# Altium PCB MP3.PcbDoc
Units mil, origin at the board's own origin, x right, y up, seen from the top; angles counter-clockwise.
Board outline 5023.23 x 3354.25 mil, 2 copper layers (Top Layer, Bottom Layer); 77 components, 66 nets, 306 pads, 116 vias.
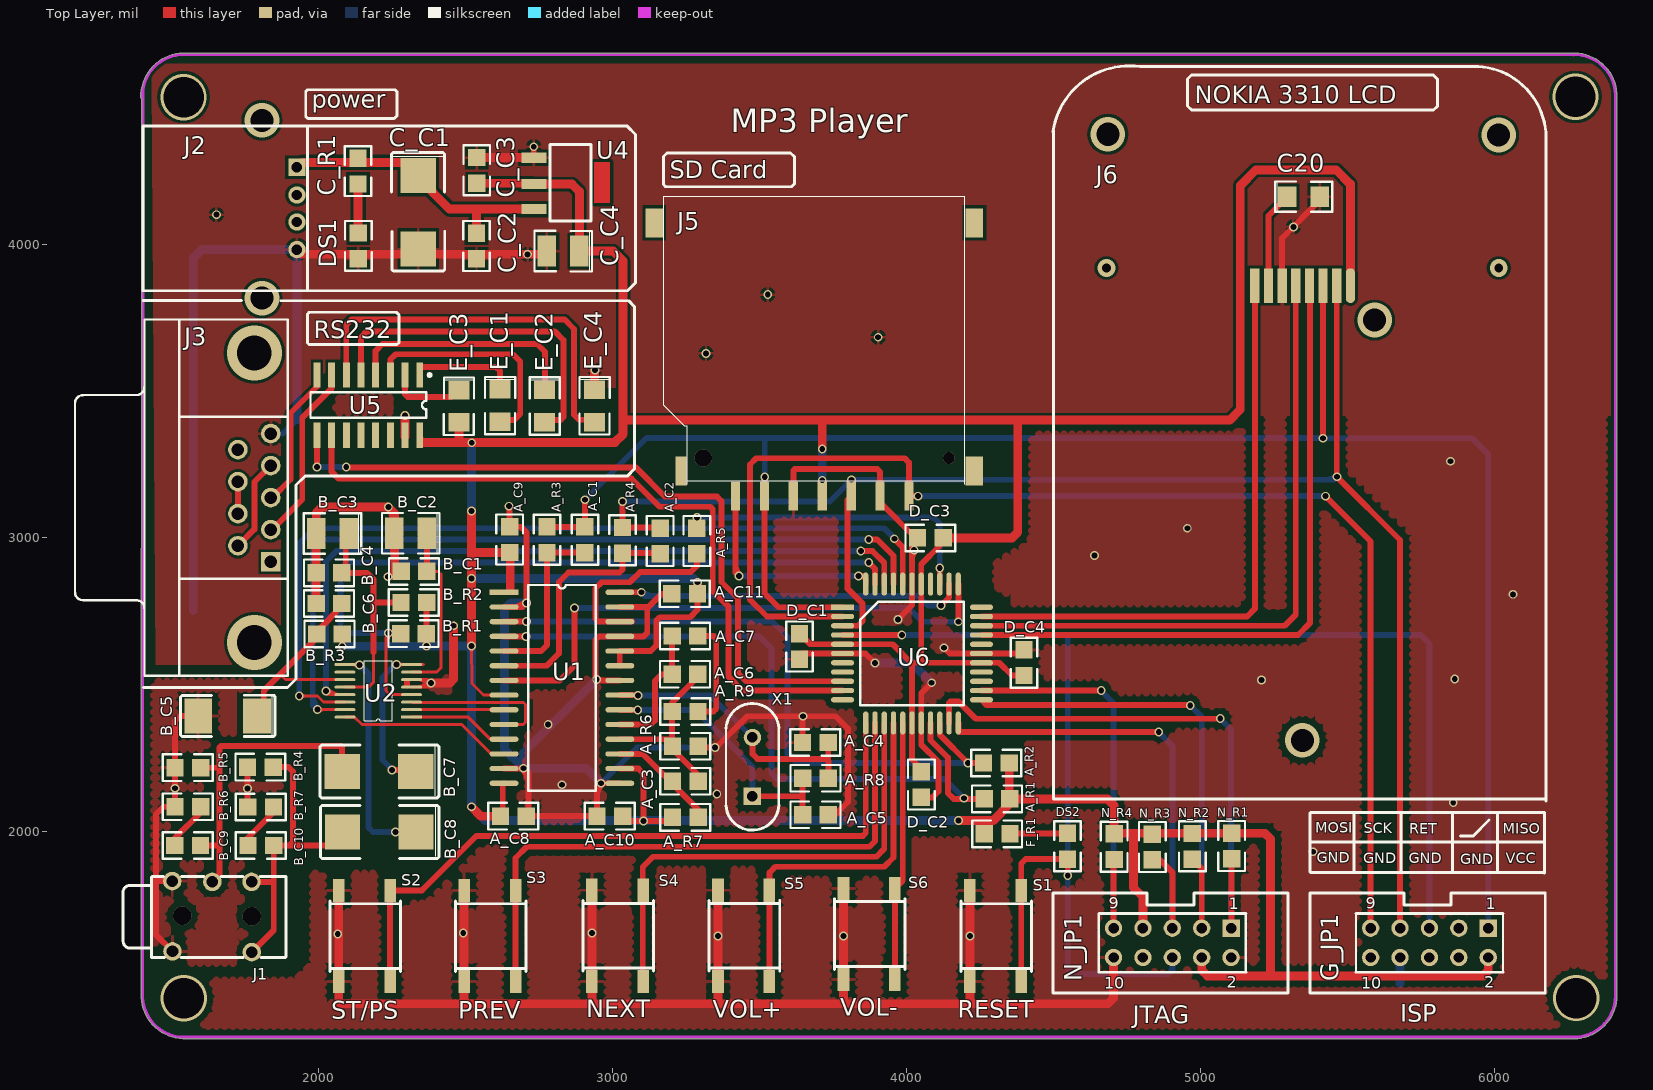
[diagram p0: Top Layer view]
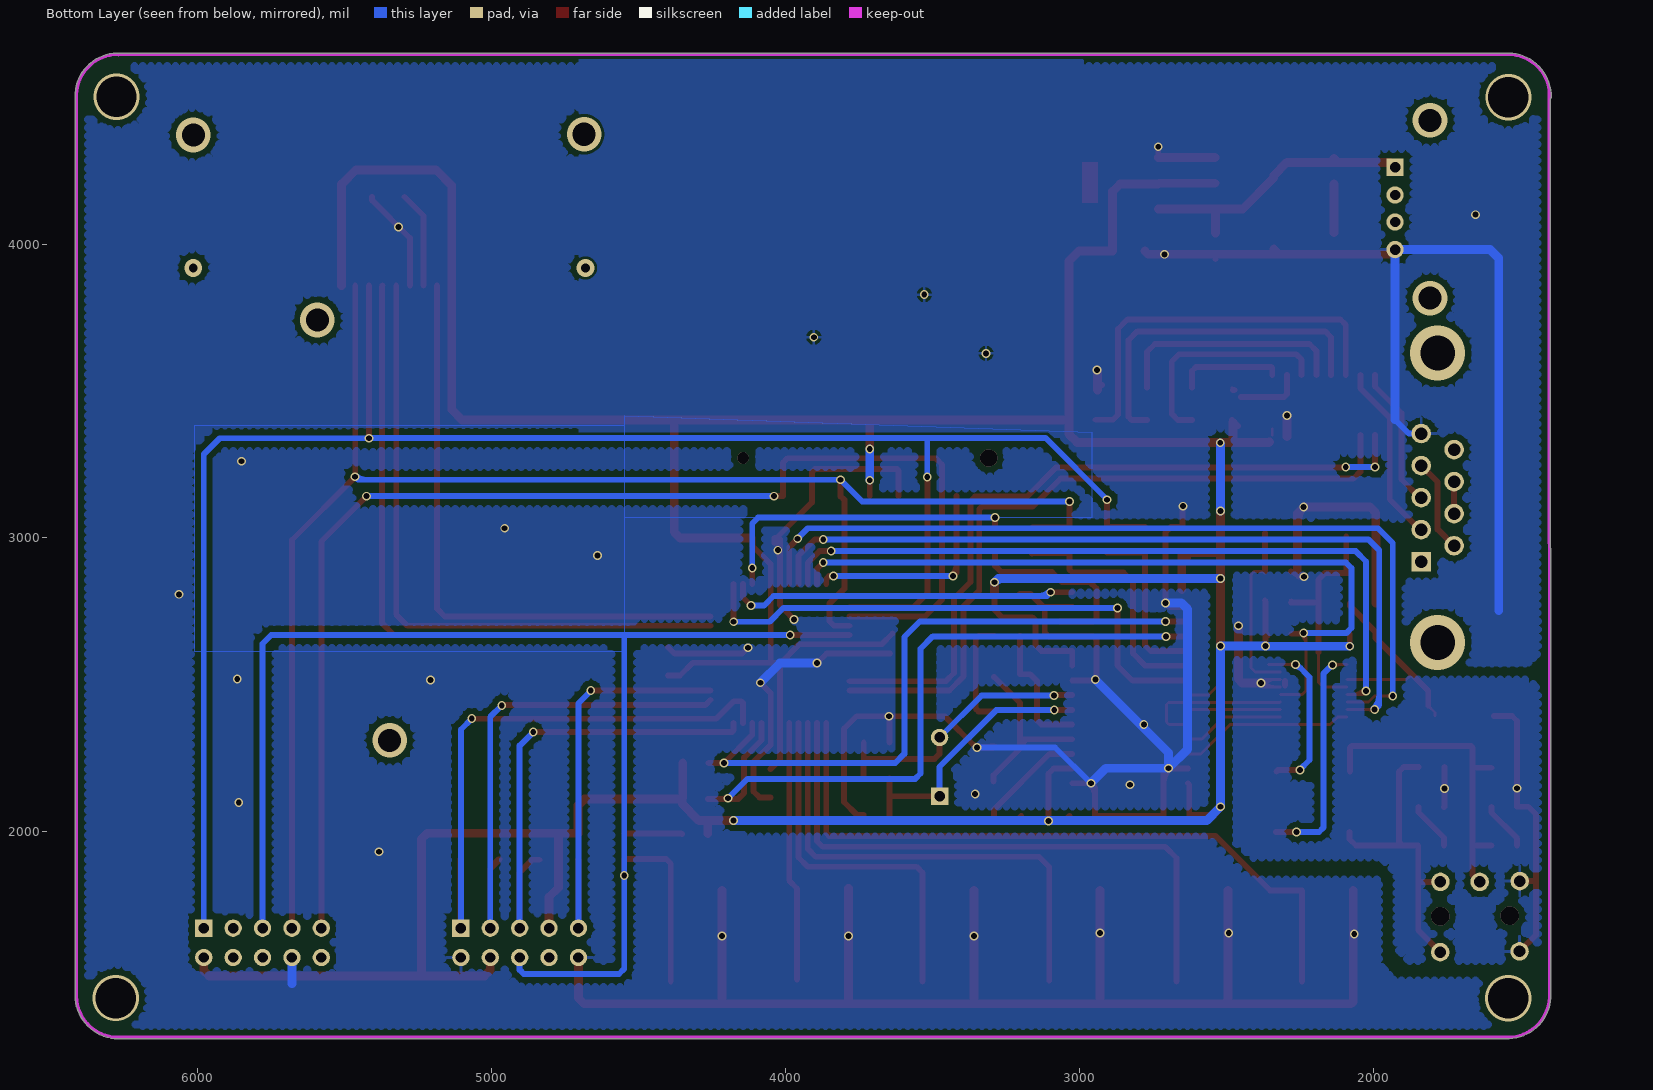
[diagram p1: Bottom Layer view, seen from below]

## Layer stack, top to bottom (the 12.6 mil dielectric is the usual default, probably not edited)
Top Layer: signal copper 1.4
Dielectric: dielectric 12.6, FR-4, Dk 4.8
Bottom Layer: signal copper 1.4

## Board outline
1395.99,1435.72 cw(c1543.5,1443.5) 1395.99,1435.74 1395.99,1435.72 ccw(c1543.5,1443.5) 1551.13,1295.98 6282,1295.98 ccw(c6282,1301) 6284.01,1296.41 ccw(c6270.5,1443.5) 6418.21,1443.5 ccw(c6270.5,1443.5) 6418.02,1451.13 6418.02,4512 ccw(c6413,4512) 6417.81,4513.43 ccw(c6270.5,4502.5) 6262.74,4650.01 ccw(c6263,4645) 6260,4649.02 1539,4650.02 ccw(c1539,4645) 1538.88,4650.01 ccw(c1542.5,4502.5) 1394.99,4498.88 ccw(c1400,4499) 1397.97,4494.41 1395.98,1436 ccw(c1401,1436)

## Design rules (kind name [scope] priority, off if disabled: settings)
Clearance [InNet('GND')] p1: gap=10
ComponentClearance [All] p1 off: gap=10 collisioncheckmode=3 verticalgap=10 showdistances=FALSE
FabricationTestPointUsage TestPointUsage [All] p1: valid=0 allowmultiple=FALSE
FabricationTestpoint Testpoint [All] p1: side=3 testpointundercomponent=TRUE minsize=40 maxsize=100 preferedsize=60 minholesize=0 maxholesize=40 preferedholesize=32 testpointgrid=1 allowsidetop=TRUE allowsidebottom=TRUE usegrid=TRUE gridtolerance=0.01
FanoutControl Fanout_LCC [All] p1 off: bgadir=Out bgaviamode=Centered fanoutstyle=Auto fanoutdirection=Alternating viagrid=1 // Protel DXP Scope 1 Expression Was: IsLCC   Fanout_LCC (Default Rule)
FanoutControl Fanout_BGA [All] p2 off: bgadir=Out bgaviamode=Centered fanoutstyle=Auto fanoutdirection=Alternating viagrid=1 // Protel DXP Scope 1 Expression Was: IsBGA   Fanout_BGA (Default Rule)
FanoutControl Fanout_SOIC [All] p3 off: bgadir=Out bgaviamode=Centered fanoutstyle=Auto fanoutdirection=Alternating viagrid=1 // Protel DXP Scope 1 Expression Was: IsSOIC   Fanout_SOIC (Default Rule)
FanoutControl Fanout_Default [All] p4: bgadir=Out bgaviamode=Centered fanoutstyle=Auto fanoutdirection=Alternating viagrid=1 // Fanout_Default (Default Rule)
FanoutControl Fanout_Small [All] p5 off: bgadir=Out bgaviamode=Centered fanoutstyle=Auto fanoutdirection=Alternating viagrid=1 // Protel DXP Scope 1 Expression Was: (CompPinCount < 5)   Fanout_Small (Default Rule)
PolygonConnect [All] p1: connectstyle=Relief reliefconductorwidth=10 reliefentries=4 polygonreliefangle="90 Angle"
RoutingVias [All] p1: holewidth=20 width=30 viastyle="Through Hole" minholewidth=20 minwidth=30 maxholewidth=20 maxwidth=30
SilkscreenOverComponentPads [All] p1: minsilkscreentomaskgap=10
SolderMaskExpansion [All] p1: expansion=4
Width [All] p1: maxlimit=30 minlimit=10 preferedwidth=10
19 further rules are at their usual default settings.

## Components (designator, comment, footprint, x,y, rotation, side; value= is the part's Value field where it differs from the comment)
A_C1 "Cap Semi" 0805 2911,2985 r270 top
A_C2 "Cap Semi" 0805 3167,2981 r270 top
A_C3 "Cap Semi" 0805 3239,2167 r180 top
A_C4 "Cap Semi" 0805 3699,2309 r0 top
A_C5 "Cap Semi" 0805 3682,2053 r180 top
A_C6 "Cap Semi" 0805 3238,2531 r180 top
A_C7 "Cap Semi" 0805 3238,2661 r180 top
A_C8 "Cap Semi" 0805 2671,2058 r0 top
A_C9 "Cap Semi" 0805 2645,3003 r90 top
A_C10 "Cap Semi" 0805 2982,2048 r180 top
A_C11 "Cap Semi" 0805 3237,2805 r180 top
A_R1 "Res3" 0805 4317,2117 r0 top
A_R2 "Res3" 0805 4315,2239 r0 top
A_R3 "Res3" 0805 2782,2985 r270 top
A_R4 "Res3" 0805 3039,2983 r270 top
A_R5 "Res3" 0805 3292,2981 r270 top
A_R6 "Res3" 0805 3239,2286 r180 top
A_R7 "Res3" 0805 3239,2044 r180 top
A_R8 "Res3" 0805 3682,2177 r180 top
A_R9 "Res3" 0805 3256,2414 r0 top
B_C1 "Cap Semi" 0805 2333,2891 r0 top
B_C2 "Cap Pol3" 1210 2233,3071 r180 top
B_C3 "Cap Pol3" 1210 1967,3070 r180 top
B_C4 "Cap Semi" 0805 2044,2886 r0 top
B_C5 "Cap Pol3" C_model 1645,2324 r180 top
B_C6 "Cap Semi" 0805 2044,2782 r0 top
B_C7 "Cap Pol3" D_model 2250,2210 r180 top
B_C8 "Cap Pol3" D_model 2251,2004 r180 top locked
B_C9 "Cap Semi" 0805 1563,1958 r0 top
B_C10 "Cap Semi" 0805 1812,1958 r0 top
B_R1 "Res3" 0805 2314,2669 r180 top
B_R2 "Res3" 0805 2315,2775 r180 top
B_R3 "Res3" 0805 2028,2668 r180 top
B_R4 "Res3" 0805 1793,2215 r180 top
B_R5 "Res3" 0805 1546,2213 r180 top
B_R6 "Res3" 0805 1546,2080 r180 top
B_R7 "Res3" 0805 1794,2079 r180 top
C20 "Cap Pol3" 1206 5387,4096 r0 top
C_C1 "Cap Pol3" D_model 2334,4153 r270 top
C_C2 "Cap Semi" 0805 2532,4002 r90 top
C_C3 "Cap Semi" 0805 2543,4242 r270 top
C_C4 "Cap Pol3" 1210 2752,4031 r180 top
C_R1 "Res3" 0805 2129,4257 r90 top
D_C1 "Cap Semi" 0805 3641,2622 r270 top
D_C2 "Cap Semi" 0805 4056,2152 r270 top
D_C3 "Cap Semi" 0805 4073,2995 r180 top
D_C4 "Cap Semi" 0805 4395,2584 r90 top
DS1 "LED" 0805 2140,3985 r270 top
DS2 "LED" 0805 4553,1942 r270 top
E_C1 "" 1206 2552,3415 r270 top
E_C2 "" 1206 2704,3414 r270 top
E_C3 "" 1206 2412,3413 r270 top
E_C4 "" 1206 2873.52,3414.48 r270 top
F_R1 "Res3" 0805 4300,1988 r180 top
G_JP1 "ISP" ISP_2 5794,2076 r0 top
J1 "Phonejack3" 耳机插座3 1287,1370 r180 top locked
J2 "USB" USB 1962,3841 r90 top
J3 "D Connector 9" 232_9PIN 1585,3205 r0 top
J5 "sd" "SD Card" 3374,3962 r0 top locked
J6 "3310" nokia3310 5394,3752 r0 top
N_JP1 "Header 5X2" ISP_2 4919,2076 r0 top
N_R1 "" 0805 5102,1960 r90 top
N_R2 "" 0805 4968,1959 r90 top
N_R3 "" 0805 4832,1957 r90 top
N_R4 "" 0805 4702,1958 r90 top
S1 "SW-DPST" key_top 4186,1725 r180 top
S2 "SW-DPST" key_top 2038,1725 r180 top
S3 "SW-DPST" key_top 2465,1725 r180 top
S4 "SW-DPST" key_top 2900,1726 r180 top
S5 "SW-DPST" key_top 3329,1726 r180 top
S6 "SW-DPST" key_top 3756,1732 r180 top
U1 "STA013" STA013 2631,2815 r0 top
U2 "1770" pcm1770 2311,2390 r180 top
U4 "CYT117" CYT117 3227,4309 r270 top
U5 "MAX232" NSO16 2169,3452 r180 top
U6 "mega16L" 贴片Mega16L 3783,2764 r0 top
X1 "晶振" jinzhen 3476,2201 r90 top

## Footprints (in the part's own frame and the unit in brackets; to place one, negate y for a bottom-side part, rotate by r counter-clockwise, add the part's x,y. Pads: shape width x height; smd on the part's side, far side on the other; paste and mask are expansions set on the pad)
232_9PIN [mm]
  rect 1.69x1.69 hole 1.09: 1(6.399,-7.267)
  round 1.69 hole 1.09: 2(6.399,-4.497) 3(6.399,-1.727) 4(6.399,1.043) 5(6.399,3.813) 6(3.559,-5.882) 7(3.559,-3.112) 8(3.559,-0.342) 9(3.559,2.428)
  silkscreen extent -10.52,-17.13 7.88,13.67
0805 [mil]
  rect 59x59 smd: 1(-52.4,-5) 2(35,-5)
  silkscreen extent -94,-50 76,40
1206 [mm]
  rect 1.6x1.8 smd: 1(-2.289,1.651) 2(0.511,1.651)
  silkscreen extent -3.37,0.35 1.59,2.97
1210 [mm]
  rect 1.6x2.7 smd: 1(-3.432,1.397) 2(-0.632,1.397)
  silkscreen extent -4.52,-0.36 0.45,3.15
C_model [mil]
  rect 94.49x118.11 smd: 1(-145,-70) 2(55,-70)
  silkscreen extent -207,-141 115,0
CYT117 [mil]
  rect 35x85 smd: 1(15,-495) 2(105,-495) 3(190,-495)
  Top Layer region: 30,-290 170,-290 170,-235 30,-235
  silkscreen extent -30,-440 230,-300
D_model [mil]
  rect 120x120 smd: 1(-80,5) 2(170,5)
  silkscreen extent -159,-86 245,95
ISP_2 [mm]
  rect 1.5x1.5 hole 0.9: 1(4.724,-10.262)
  round 1.5 hole 0.9: 2(4.724,-12.802) 3(2.184,-10.262) 4(2.184,-12.802) 5(-0.356,-10.262) 6(-0.356,-12.802) 7(-2.896,-10.262) 8(-2.896,-12.802) 9(-5.436,-10.262) 10(-5.436,-12.802)
  silkscreen extent -10.67,-15.88 9.65,-7.24
jinzhen [mm]
  rect 1.5x1.5 hole 0.9: 1(-2.032,0)
  round 1.5 hole 0.9: 2(3.048,0)
  silkscreen extent -4.97,-2.29 5.98,2.29
key_top [mm]
  rect 1x2 smd: 1(-5.207,5.969) 2(-0.762,5.969) 3(-5.207,-1.905) 4(-0.762,-1.905)
  silkscreen extent -6.1,-1.02 0,5.08
nokia3310 [mm]
  oval 0.8x3 smd: 1(2.972,2.702)
  rect 0.8x3 smd: 2(1.792,2.702) 3(0.612,2.702) 4(-0.568,2.702) 5(-1.748,2.702) 6(-2.928,2.702) 7(-4.108,2.702) 8(-5.288,2.702)
  silkscreen extent -22.74,-41.83 19.89,21.7
NSO16 [mm]
  rect 0.6x2.2 smd: 1(-4.445,-2.6) 2(-3.175,-2.6) 3(-1.905,-2.6) 4(-0.635,-2.6) 5(0.635,-2.6) 6(1.905,-2.6) 7(3.175,-2.6) 8(4.445,-2.6) 9(4.445,2.6) 10(3.175,2.6) 11(1.905,2.6) 12(0.635,2.6) 13(-0.635,2.6) 14(-1.905,2.6) 15(-3.175,2.6) 16(-4.445,2.6)
  silkscreen extent -5.42,-2.72 5,1.1
pcm1770 [mm]
  rect 1.8x0.25 smd: 1(-0.127,0)
  oval 1.8x0.25 smd: 2(-0.127,-0.65) 3(-0.127,-1.3) 4(-0.127,-1.95) 5(-0.127,-2.6) 6(-0.127,-3.25) 7(-0.127,-3.9) 8(-0.127,-4.55) 9(5.627,-4.55) 10(5.627,-3.9) 11(5.627,-3.25) 12(5.627,-2.6) 13(5.627,-1.95) 14(5.627,-1.3) 15(5.627,-0.65) 16(5.627,0)
  silkscreen extent 1.53,-4.88 3.97,0.33
"SD Card" [mm]
  rect 1.5x2.5 smd: 0(-5.9,2.794) 0(21.77,-18.669) 0(21.78,2.794)
  rect 1x2.5 smd: 0(-3.556,-18.669)
  rect 0.8x2.5 smd: 1(1.129,-20.828) 2(3.629,-20.828) 3(6.129,-20.828) 4(8.629,-20.828) 5(11.129,-20.828) 6(13.629,-20.828) 7(16.129,-20.828)
  silkscreen extent -5.08,-19.81 20.95,5.08
STA013 [mm]
  rect 2.5x0.45 smd: 1(0,0)
  oval 2.5x0.45 smd: 2(0,-1.27) 3(0,-2.54) 4(0,-3.81) 5(0,-5.08) 6(0,-6.35) 7(0,-7.62) 8(0,-8.89) 9(0,-10.16) 10(0,-11.43) 11(0,-12.7) 12(0,-13.97) 13(0,-15.24) 14(0,-16.51) 15(10,-16.51) 16(10,-15.24) 17(10,-13.97) 18(10,-12.7) 19(10,-11.43) 20(10,-10.16) 21(10,-8.89) 22(10,-7.62) 23(10,-6.35) 24(10,-5.08) 25(10,-3.81) 26(10,-2.54) 27(10,-1.27) 28(10,0)
  silkscreen extent 2.08,-17.14 7.92,0.64
USB [mm]
  rect 1.5x1.5 hole 0.9: 1(10.668,0.914)
  round 1.5 hole 0.9: 2(8.28,0.914) 3(5.944,0.914) 4(3.556,0.914)
  silkscreen extent 0,0 14.22,14.22
耳机插座3 [mm]
  round 1.6 hole 1: 1(-12.329,-5.594) 1(-12.309,-11.669) 2(-8.917,-11.669) 3(-5.474,-5.664) 3(-5.454,-11.739)
  silkscreen extent -15.28,-12.15 -1.19,-5.12
贴片Mega16L [mm]
  rect 2x0.45 smd: 1(0,0)
  oval 2x0.45 smd: 2(0,-0.8) 3(0,-1.6) 4(0,-2.4) 5(0,-3.2) 6(0,-4) 7(0,-4.8) 8(0,-5.6) 9(0,-6.4) 10(0,-7.2) 11(0,-8) 23(12,-8) 24(12,-7.2) 25(12,-6.4) 26(12,-5.6) 27(12,-4.8) 28(12,-4) 29(12,-3.2) 30(12,-2.4) 31(12,-1.6) 32(12,-0.8) 33(12,0)
  oval 0.45x2 smd: 12(2,-10) 13(2.8,-10) 14(3.6,-10) 15(4.4,-10) 16(5.2,-10) 17(6,-10) 18(6.8,-10) 19(7.6,-10) 20(8.4,-10) 21(9.2,-10) 22(10,-10) 34(10,2) 35(9.2,2) 36(8.4,2) 37(7.6,2) 38(6.8,2) 39(6,2) 40(5.2,2) 41(4.4,2) 42(3.6,2) 43(2.8,2) 44(2,2)
  silkscreen extent 1.54,-8.47 10.47,0.47

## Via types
v1: diameter 30, hole 20, Top Layer to Bottom Layer, tented both sides, 96 vias
v2: diameter 118.11, hole 78.74, Top Layer to Bottom Layer, 6 vias
v3: diameter 157.48, hole 137.8, Top Layer to Bottom Layer, 3 vias
v4: diameter 60, hole 30, Top Layer to Bottom Layer, 2 vias
v5: diameter 187.4, hole 118.11, Top Layer to Bottom Layer, 2 vias
v6: diameter 62.99, hole 62.99, Top Layer to Bottom Layer, 2 vias
v7: diameter 30, hole 20, Top Layer to Bottom Layer, 2 vias
v8: diameter 39.37, hole 39.37, Top Layer to Bottom Layer, 1 vias
v9: diameter 59.06, hole 59.06, Top Layer to Bottom Layer, 1 vias
v10: diameter 157.48, hole 137.79, Top Layer to Bottom Layer, 1 vias

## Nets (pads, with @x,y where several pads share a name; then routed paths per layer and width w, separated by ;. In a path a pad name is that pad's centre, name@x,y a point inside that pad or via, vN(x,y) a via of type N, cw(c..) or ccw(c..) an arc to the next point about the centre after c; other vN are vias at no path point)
3310_DC: J6.4 U6.30 | length 2284.1
  Top Layer w20: U6.30 5332.51,2669.51 5374,2711 5374,3856.03 J6.4
3310_RES: J6.8 U6.32 | length 2040.8
  Top Layer w20: U6.32 5159.5,2732.5 5185.82,2758.82 J6.8
3310_SCE: J6.5 U6.31 | length 2204.9
  Top Layer w20: U6.31 5287.2,2701.01 5325.19,2739 J6.5
BACK: S3.1 S3.3 U6.13 | length 2070.1
  Top Layer w20: S3.1 2670,1911 2708,1949 3874.24,1949 3893.24,1968 U6.13
GND: A_C4.1 A_C5.1 A_C8.2 A_C9.2 A_C10.2 A_C11.2 A_R6.1 B_C1.1 B_C2.2 B_C3.2 B_C4.1 B_C5.2 B_C6.1 B_R4.2 B_R5.2 B_R6.2 B_R7.2 C20.2 C_C1.2 C_C2.1 C_C3.1 C_C4.2 D_C1.2 D_C2.2 D_C3.2 D_C4.2 DS1.2 E_C4.1 G_JP1.8 J1.3 J2.4 J3.5 J5.3 J5.6 J6.6 N_JP1.2 N_JP1.10 S1.2 S1.4 S2.2 S2.4 S3.2 S3.4 S4.2 S4.4 S5.2 S5.4 S6.2 S6.4 U1.2 U1.13 U1.15 U1.22 U1.25 U1.27 U2.5 U2.6 U4.1 U5.15 U6.6 U6.18 U6.28 U6.39 | length 19093.6
  Top Layer w10: B_C1.1@2265,2885 B_C1.1@2279.6,2885 ; U2.5 2368.36,2492.36 ; U2.6 2370.05,2517.95 ; U2.5@2324.93,2492.36 ccw(c2324.93,2563.07) v1@2374.93,2513.07 ; U2.6@2329,2517.95 cw(c2329,2453) v1@2374.93,2498.93 ; U2.5@2349.08,2492.36 ccw(c2349.08,2538.92) v1(2382,2506) ; 2353.14,2517.95 cw(c2353.14,2477.14) v1(2382,2506) ; v1@2372.15,2504.3 cw(c2358.75,2501.98) 2368.36,2492.36 ; v1@2372.4,2508.79 ccw(c2363.48,2511.39) 2370.05,2517.95 ; 2373.22,2492.36 ccw(c2373.22,2514.78) v1@2389.07,2498.93 ; v1@2379.21,2515.6 cw(c2376.61,2524.52) 2370.05,2517.95 ; v1@2380.3,2496.15 ccw(c2377.98,2482.75) 2368.36,2492.36 ; 2368.36,2492.36 v1(2382,2506) ; 2370.05,2517.95 v1(2382,2506)
  Top Layer w20: 1446,1838 1451.84,1832.16 J1.3@1501.73,1832.16 ; J1.3@1502.52,1598.48 1502.52,1593 1446,1649.52 1446,2059 1472,2085 B_R6.2 1511,2377 1528,2394 B_C5.2 ; B_R4.2 1758,2085 B_R7.2 ; B_C6.1@1991,2777.6 B_C6.1 ; v1(2236,2868) 2259,2873 B_C1.1@2275,2885 ; v1@2236.71,2872.95 ccw(c2243.15,2918.02) B_C1.1@2270.46,2881.6 ; v1@2239.24,2871.81 ccw(c2248.3,2882.5) B_C1.1@2256.71,2871.28 ; B_C1.1@2279.6,2885 B_C1.1 ; 2300,2498 2300,2512.95 ; C_C2.1@2536.6,3950 C_C2.1 ; U1.13 v1@2697,2215 ; U1.2 2693,2765 v1(2707,2779) 2707,3019 2688,3038 A_C9.2 2650,3106 v1(2648,3108) ; v1@2644.46,3104.46 cw(c2631.1,3091.1) 2650,3091.1 ; U1.2@2661.13,2765 ccw(c2661.13,2824.87) v1@2703.46,2782.54 ; v1@2693.46,2212.46 cw(c2643.89,2162.89) 2714,2162.89 ; v1@2696.56,2211.02 cw(c2694.86,2191.96) 2714,2191.96 ; v1@2698,2215 2714,2199 A_C8.2@2714,2053 ; A_C8.2@2714,2050 2717,2053 A_C10.2 2947,2151 v1(2961,2165) U1.15 ; U4.1@2731.6,4294.4 U4.1 v1(2732,4331) ; E_C4.1@2923,3520.12 E_C4.1 ; S4.4@2928,1801 S4.4@2928,1803 ; 2930,1415 2930,1417 ; 2942,2539.73 ccw(c2967.73,2539.73) 2949.54,2521.54 ccw(c2965.31,2537.31) 2965.31,2515 ; 2947,2119.13 cw(c3006.87,2119.13) v1@2964.54,2161.46 ; 2947,2145.2 cw(c2961.82,2145.2) v1@2961.21,2160 ; U1.22 2949,2515 2942,2522 2942,2653 2954,2665 3106,2665 3118,2677 3118,2761 3167,2810 A_C11.2 ; U1.27 3114,2765 ; A_R6.1@3300,2291 A_R6.1 3295.4,2287 v1(3349,2287) ; v1@3349,2292 ccw(c3349,2311.31) 3362.66,2297.66 ; v1@3352,2287 3458,2393 3759,2393 3801,2351 3801,2101 3758,2058 A_C5.1 ; J5.3 3615.3,3229.3 3620,3234 3901,3234 3910.57,3224.43 3910.57,3120.43 4031,3000 D_C3.2 D_C3.2@4038,2982.78 ; D_C1.2@3644.52,2606.52 3860.48,2606.52 v1(3893,2574) ; A_C4.1 v1@3646.6,2392.6 ; 3646.6,2377.54 cw(c3663.46,2377.54) v1@3651.54,2389.46 ; 3788,1416 3788,1425 ; v1(3971,2722) 3985,2736 3985,2737 4019.22,2771.22 4019.22,2995.22 D_C3.2@4025,3001 ; 4019.22,2928.72 cw(c4055.94,2928.72) v1@4029.98,2954.68 ; v1@4019.22,2951 v1(4026.44,2958.22) ; D_C3.2@4019.22,2987.72 ccw(c4055.94,2987.72) v1@4029.98,2961.75 ; D_C2.2 4089,2117 4109,2137 4109,2238 4050.72,2296.28 4050.72,2471.72 v1(4086,2507) ; v1(4128,2626) 4147.48,2606.52 4378.52,2606.52 D_C4.2@4400,2628 ; 4205,1415 4216,1426 4216,1431 ; J6.6 5278.73,4020.31 5407.12,4148.69 C20.2
  Top Layer w30: J2.4@1938,3981 J2.4 1942,3965 2765.88,3965 C_C4.2 ; B_C6.1@1991,2777.6 B_C3.2@1991,3015 ; B_C3.2 1991.88,3085.88 2011,3105 v1(2237,3105) ; S2.4 2068,1422 2075,1415 4686,1415 4705,1434 N_JP1.10 ; B_C1.1@2258.94,2885.9 2258.32,3016 2258,3084 v1(2237,3105) ; U5.15@2294,3344 v1(2294,3417) ; C_C1.2@2321,3965 C_C1.2 ; v1(2382,2506) 2446,2506 2459,2519 v1(2459,2701) ; 2480.51,1415 ccw(c2480.51,1435.49) 2495,1421 ; S3.4 2495,1421 ; 2509.49,1415 cw(c2509.49,1435.49) 2495,1421 ; C_C3.1 U4.1@2731.6,4294.4 ; 2930,1417 S4.4 ; E_C4.1@2939,3503 2939,3570 v1(2940,3571) ; 3359,1416 S5.4 ; 3786,1425 S6.4 ; 4216,1431 S1.4 ; v1(2237,3105) cw(c2186.78,3054.3) 2258.14,3054.64 ccw(c2186.78,3054.3) v1(2237,3105)
  Bottom Layer w20: J3.5 1879.11,3355.11 1926,3402 ; v1(2961,2165) 3083,2287 v1(3349,2287)
  Bottom Layer w30: 1573,2752 1573,3952 1602,3981 J2.4 1926,3402 ; v1(2707,2779) 2654,2779 2632,2757 2632,2281 v1(2697,2216) ; v1(2946,2518) 2697,2269 v1(2697,2216) ; v1(2961,2165) 2910,2216 v1(2697,2216) ; v1(3893,2574) 4019,2574 v1(4086,2507) ; 5680,1484 G_JP1.8
  other v1: 3359,1645 3786,1645 4216,1645 2065,1652 2492,1655 2930,1656 5384,1932 5861,2100 3354.9,2128 1758,2147 1511,2148 2828,2160 2781,2365 3648,2393 5208,2516 5866,2520 6064,2808 4640,2940 4956,3033 5852,3261 3318,3628 3904,3683 3528,3828 2711,3965 5316.9,4058.47 1652,4100
HIGH: S5.1 S5.3 U6.15 | length 1271.5
  Top Layer w20: S5.1 3534,1861 3554,1881 3925,1881 3956.23,1912.23 U6.15
LEW: S6.1 S6.3 U6.16 | length 884.4
  Top Layer w20: S6.1 S6.3 3987.72,1833.72 U6.16
LRCKT: U1.11 U2.1 | length 346.1
  Top Layer w10: U2.1 2509,2390 2584,2315 U1.11
MC: U2.14 U6.40 | length 2964.2
  Top Layer w10: v1(1934,2462) 1996,2462 2016.82,2441.18 U2.14 ; v1@1941.07,2454.93 cw(c1958.14,2437.86) 1958.14,2462 cw(c1958.14,2486.14) v1@1941.07,2469.07
  Top Layer w20: v1(3959,2997) 3987.72,2968.28 U6.40
  Bottom Layer w20: v1(1934,2462) 1934,2983 1984,3033 3925,3033 3959,2999 v1(3959,2997) ; 3949.05,3008.95 cw(c3937.1,2997) v1@3954,2997
MD: U2.13 U6.42 | length 2619.2
  Top Layer w10: v1@2027.6,2469.34 cw(c2030.19,2459.74) 2037.23,2466.77 ; v1@2032.07,2486.07 ccw(c2078.66,2532.66) U2.13@2078.66,2466.77 ; v1@2034.66,2476.4 ccw(c2044.26,2473.81) 2037.23,2466.77 ; U2.13@2054.52,2466.77 cw(c2054.52,2508.52) v1(2025,2479) 2037.23,2466.77 ; U2.13 2037.23,2466.77
  Top Layer w20: v1(3845,2955) 3885,2955 3924.73,2915.27 U6.42
  Bottom Layer w20: v1(2025,2479) 2025,2920 2060,2955 v1(3845,2955)
MISO: G_JP1.9 J5.7 U6.2 | length 4419.5
  Top Layer w20: U6.2 3525.5,2732.5 3468,2790 3468,3250 3489,3271 3994,3271 4009,3256 J5.7 v1(4040,3142) ; v1(5426,3142) 5580,2988 G_JP1.9
  Bottom Layer w20: v1(4040,3142) v1(5426,3142)
MOSI: A_C1.1 A_R3.1 G_JP1.1 J5.2 J6.3 U6.1 | length 6349.1
  Top Layer w20: A_R3.1 A_C1.1 v1(2906,3130) ; v1@3516.87,3205.87 3516.87,2812.13 3565,2764 U6.1 ; v1@5417.1,3340 5417.1,3857.38 J6.3
  Bottom Layer w20: v1(2906,3130) 2906,3131 3115,3340 v1@5417.1,3340 ; v1(3518,3207) 3518,3340 ; v1(5418.1,3339) 5926,3339 5980,3285 G_JP1.1
MS: U2.15 U6.41 | length 2842.4
  Top Layer w10: v1(1995.41,2415.59) U2.15 ; v1@2002.48,2408.52 cw(c2019.55,2391.45) 2019.55,2415.59 cw(c2019.55,2439.73) v1@2002.48,2422.66
  Top Layer w20: v1(3872,2995) 3900,2995 3956.23,2938.77 U6.41
  Bottom Layer w20: 1980,2464.86 ccw(c2044.68,2464.86) v1@1998.94,2419.13 ; v1(1995.41,2415.59) 1980,2431 1980,2958 2017,2995 v1(3872,2995)
NetA_C1_2: A_C1.2 A_R3.2 U1.5 | length 598.3
  Top Layer w20: U1.5 2757,2615 2777,2635 A_R3.2 A_C1.2
NetA_C2_2: A_C2.2 A_R4.2 U1.6 | length 865.6
  Top Layer w20: U1.6 2776,2565 2818,2607 2818,2850 2850,2882 3024,2882 3034,2892 A_R4.2 3160,2948 A_C2.2
NetA_C3_1: A_C3.1 A_C6.1 A_R6.2 A_R9.1 U1.18 | length 640.1
  Top Layer w20: U1.18 3199.6,2315 A_R6.2@3202.6,2318 ; A_R6.2@3180,2315 A_R6.2 3204,2281 3292.4,2192.6 A_C3.1@3292.4,2171 ; A_R6.2@3202.6,2292.4 3202.6,2438.6 A_C6.1@3290.4,2526.4
NetA_C3_2: A_C3.2 A_R7.1 U1.17 | length 372.3
  Top Layer w20: U1.17 3102,2265 3290.4,2076.6 A_R7.1@3290.4,2048
NetA_C4_2: A_C4.2 A_R8.1 U1.21 X1.2 | length 954.6
  Top Layer w20: U1.21 3086,2465 v1(3087,2464) ; X1.2 3476,2265 3493,2248 3734,2248 ; A_R8.1@3734,2182.4 A_R8.1 A_C4.2
  Bottom Layer w20: v1(3087,2464) 3333,2464 X1.2
NetA_C5_2: A_C5.2 A_R8.2 U1.20 X1.1 | length 927.9
  Top Layer w20: U1.20 3025.7,2414 v1(3086,2414) ; X1.1 3644,2121 3647,2124 ; A_C5.2 A_R8.2
  Bottom Layer w20: v1(3086,2414) 3283,2414 3476,2221 X1.1
NetA_C6_2: A_C6.2 A_C7.2 U1.19 | length 457
  Top Layer w20: U1.19 3130,2365 3144,2379 3144,2512 3168,2536 A_C6.2 A_C7.2
NetA_C7_1: A_C7.1 A_R9.2 | length 370.9
  Top Layer w20: A_R9.2@3290,2409 3343,2409 3353,2419 3353,2656 3343,2666 A_C7.1
NetA_R5_2: A_R5.2 U1.26 | length 650
  Top Layer w20: U1.26@3067,2715 2952,2715 2942,2725 2942,2828 2963,2849 3059,2849 3094,2884 3266,2884 3287,2905 A_R5.2
NetB_C1_2: B_C1.2 B_C2.1 U2.7 | length 607.3
  Top Layer w10: U2.7 2402,2543.54 2417,2558.54 2417,2875 2406,2886 B_C1.2
  Top Layer w20: B_C1.2 2368,3015.88 B_C2.1
NetB_C3_1: B_C3.1 B_C4.2 B_R2.2 U2.12 | length 946.2
  Top Layer w10: B_C4.2 B_C4.2@2081,2881 ; U2.12 2170.36,2492.36 2186,2508 2186,2778
  Top Layer w20: B_C4.2 2164,2881 2186,2859 2186,2611 ; B_C4.2@2092,2892 B_C3.1@2092,3004.88 ; 2186,2780 B_R2.2 ; B_R2.2@2278.88,2784.12 B_R2.2@2279,2784
NetB_C5_1: B_C5.1 B_C6.2 B_R3.2 U2.11 | length 727.8
  Top Layer w10: B_C5.1 1790,2406 B_C5.1@1813,2429 ; 1874.7,2530.7 1887.44,2517.95 U2.11
  Top Layer w20: B_C5.1@1813,2429 1813,2480 1993,2660 B_R3.2@1993,2682 ; B_R3.2@1992,2673 B_R3.2@1992,2677 ; B_R3.2@1993,2681 2038.92,2726.92 2038.92,2727.92 2079,2768 B_C6.2
NetB_C7_2: B_C7.2 B_C9.2 B_R5.1 J1.2 | length 1096.9
  Top Layer w20: B_C9.2 1660,1953 ; B_R5.1 1660,2218 1662,2220 ; J1.2 1662,1853.35 1662,2286 1668,2292 2074,2292 2080,2286 B_C7.2
NetB_C8_2: B_C8.2 B_C10.2 B_R4.1 J1.1 | length 1082.7
  Top Layer w20: J1.1@1771.62,1829.41 1841.41,1829.41 1847,1835 ; J1.1@1771.75,1590.25 J1.1@1786.25,1590.25 ; J1.1@1772.41,1590.25 1847,1664.84 B_C10.2 2059,1953 2081,1975 B_C8.2 ; B_R4.1 1897,2220 1912,2205 1912,1965 1900,1953
NetB_C9_1: B_C9.1 B_R6.1 | length 168.4
  Top Layer w20: B_C9.1 1510.6,1977.6 1598.4,2065.4 B_R6.1
NetB_C10_1: B_C10.1 B_R7.1 | length 167
  Top Layer w20: B_C10.1 1759.6,1979.6 1846.4,2066.4 B_R7.1
NetC20_1: C20.1 J6.7 | length 329.4
  Top Layer w20: J6.7 5232.28,4096.4 C20.1
NetC_C1_1: C_C1.1 C_C2.2 C_R1.2 J2.1 U4.3 | length 989.6
  Top Layer w20: 2537,4116 2537,4119
  Top Layer w30: J2.1 1943,4278 2294,4278 C_C1.1 2339,4225 2445,4119 U4.3 ; C_R1.2@2120,4278 C_R1.2 ; C_C2.2 2537,4116 2540,4119
NetC_R1_1: C_R1.1 DS1.1 | length 167.6
  Top Layer w20: DS1.1@2134,4038.4 DS1.1
  Top Layer w30: DS1.1@2134,4038.4 C_R1.1
NetDS2_1: DS2.1 F_R1.1 | length 196.2
  Top Layer w20: F_R1.1 4353.8,1994.4 DS2.1
NetE_C1_1: E_C1.1 U5.1 | length 360.1
  Top Layer w20: U5.1 2344,3578 2347,3581 2604,3581 2617,3568 E_C1.1@2617,3511.12
NetE_C1_2: E_C1.2 U5.3 | length 768.2
  Top Layer w20: U5.3 2244,3607 2262,3625 2661,3625 2686,3600 2686,3422 2664.88,3400.88 E_C1.2@2617,3400.88
NetE_C2_1: E_C2.1 U5.4 | length 801.2
  Top Layer w20: U5.4 2194,3637 2217,3660 2743,3660 2770,3633 E_C2.1@2770,3511.12
NetE_C2_2: E_C2.2 U5.5 | length 1167
  Top Layer w20: U5.5 2144,3683 2164,3703 2803,3703 2833,3673 2833,3412 2821.88,3400.88 E_C2.2@2770,3400.88
NetE_C3_1: E_C3.1 U5.2 | length 230.1
  Top Layer w10: E_C3.1@2481,3510 E_C3.1@2481,3511.12
  Top Layer w20: U5.2 2294,3489 2303,3480 E_C3.1@2449.88,3480 ; E_C3.1@2473,3503.12 E_C3.1
NetE_C4_2: E_C4.2 U5.6 | length 1342.4
  Top Layer w20: U5.6 2094,3725 2112,3743 2837,3743 2869,3711 2869,3419 2886.12,3401.88 E_C4.2@2946,3401.88
NetJ3_2: J3.2 U5.7 | length 614.5
  Top Layer w20: J3.2 1840.94,3027.94 1944,3131 1944,3409 2044,3509 U5.7
NetJ3_3: J3.3 U5.8 | length 485.4
  Top Layer w20: J3.3 1842,3137 1904,3199 1904,3425 1994,3515 U5.8
NetJ3_4: J3.4 J3.6 | length 319.1
  Top Layer w20: J3.6 1725.42,2973.42 1781,3029 1781,3190.13 J3.4
NetJ3_7: J3.7 J3.8 | length 109.1
  Top Layer w20: J3.7 J3.8
NEXT: S4.1 S4.3 U6.14 | length 1662.9
  Top Layer w20: S4.1@3103,1493 3103,1880 3138,1915 3898,1915 3924.73,1941.73 U6.14
OCLK: U1.12 U2.16 | length 593.3
  Top Layer w10: U2.16 2122,2390 2147,2365 2487,2365 2587,2265 U1.12
PD: B_R1.2 U2.4 U6.43 | length 2692
  Top Layer w10: 2229,2632.54 cw(c2280.46,2632.54) v1@2244.07,2668.93 ; 2229,2656.69 cw(c2256.31,2656.69) v1(2237,2676) ; 2229,2657.21 cw(c2237.81,2657.21) v1@2237.43,2666.01 ; v1@2244,2674 2229,2659 2229,2480 2242.23,2466.77 U2.4 ; B_R1.2@2278,2678 2278,2674 B_R1.2
  Top Layer w20: v1(2237,2676) 2239,2674 B_R1.2 ; v1@2240.54,2679.54 ccw(c2253.9,2692.9) B_R1.2@2253.9,2674 ; v1(3872.06,2915.94) 3893.24,2894.76 U6.43
  Bottom Layer w20: v1(2237,2676) 2092,2676 2074,2694 2074,2897 2092.94,2915.94 v1(3872.06,2915.94)
PLAY/STOP: S2.1 S2.3 U6.12 | length 2384.2
  Top Layer w20: S2.1 S2.3 2351,1800 2537,1986 3851.74,1986 3861.74,1996 U6.12
RESET: DS2.2 G_JP1.5 N_JP1.6 S1.1 S1.3 U6.4 | length 5145.6
  Top Layer w20: U6.4 v1(3984.49,2669.51) ; S1.1 4391,1892 4406,1907 DS2.2 4549,1906 v1(4549,1851)
  Bottom Layer w20: v1(3984.49,2669.51) 5750.49,2669.51 5780,2640 G_JP1.5 ; 4549,2669.51 4549,1534 4567,1516 4891,1516 4905,1530 N_JP1.6
RXD: U5.9 U6.9 | length 2506.1
  Top Layer w20: v1(1994,3241) U5.9 ; v1@2097,3240 3079,3240 3178,3141 3355,3141 3371,3125 3371,2850 3427,2794 3427,2540 3454.97,2512.03 U6.9
  Bottom Layer w20: v1(1994,3241) v1(2094,3241)
SCK: A_C2.1 A_R4.1 G_JP1.7 J5.5 J6.2 U6.3 | length 5578.9
  Top Layer w20: v1(3034,3124) A_R4.1 3160,3035.4 A_C2.1 ; U6.3 3835.01,2701.01 3851,2717 3851,2776 3800,2827 3800,3129.85 J5.5@3813,3142.85 ; J5.5@3813,3141 v1(3813,3198) ; v1@5464.56,3208 J6.2 ; v1(5465,3208) 5680,2993 G_JP1.7
  Bottom Layer w20: v1(3034,3124) 3739,3124 v1(3813,3198) 5455,3198 v1(5465,3208) ; 5428.79,3198 ccw(c5428.79,3244.21) v1@5461.46,3211.54
SCKT: U1.10 U2.3 | length 527.7
  Top Layer w10: U2.3 2317.18,2440 2697,2440 2704,2433 2704,2373 2696,2365 U1.10
SD_CS: J5.1 U6.44 | length 771.5
  Top Layer w20: 3418.45,2911.04 ccw(c3471.49,2911.04) v7@3433.98,2873.54 ; J5.1 3418.45,2882 v7(3430.45,2870) ; v1(3837,2870) 3852,2870 3861.74,2860.26 U6.44
  Bottom Layer w20: v7(3430.45,2870) v1(3837,2870)
SDO: U1.9 U2.2 | length 314.4
  Top Layer w10: U2.2 U1.9@2630.41,2415.59
STA_EN: U1.7 U6.34 | length 1913.5
  Top Layer w20: U1.7 2820,2515 2871,2566 v1(2871,2762) ; v1(4176.7,2714.7) U6.34
  Bottom Layer w20: v1@2871,2764 v1(2871,2762) 4007,2762 4054.3,2714.7 v1(4176.7,2714.7) v1@4176.7,2713.7
STA_REQ: U1.28 U6.35 | length 1240.3
  Top Layer w20: U1.28 v1(3098,2815) ; v7(4118,2770) 4145.21,2797.21 U6.35
  Bottom Layer w20: v1(3098,2815) 3111,2802 4041,2802 4073,2770 v7(4118,2770) ; v1@3101.54,2818.54 ccw(c3141.46,2858.46) 3141.46,2802
STA_RESET: A_R5.1 U6.36 | length 1078.7
  Top Layer w20: A_R5.1 v1(3287,3069) ; U6.36 v1(4113.71,2897.71)
  Bottom Layer w20: v1(3287,3069) 4093.71,3069 4113.71,3049 v1(4113.71,2897.71) v1@4115,2899
STA_SCL: A_R1.1 U1.4 U6.19 | length 2467.2
  Top Layer w20: U1.4 v1(2706,2665) ; U6.19 4082.21,2311.79 4141,2253 4141,2132 4161,2112 v1@4196,2112 ; 4179.1,2112 ccw(c4179.1,2130.9) v1@4192.46,2117.54 ; v1(4196,2114) 4198,2112 A_R1.1 ; v1@4199.54,2117.54 ccw(c4212.9,2130.9) 4212.9,2112
  Bottom Layer w20: v1(2706,2665) 3499,2665 3541,2623 3541,2198 3559,2180 4130,2180 v1(4196,2114)
STA_SDA: A_R2.1 U1.3 U6.20 | length 2239.6
  Top Layer w20: U1.3 v1@2706,2715 ; U6.20 4113.71,2330.29 v1(4210,2234) A_R2.1
  Bottom Layer w20: v1(2707,2716) 3543,2716 3596,2663 3596,2265 3627,2234 v1(4210,2234)
TCK: N_JP1.1 N_R1.1 U6.21 | length 1984.4
  Top Layer w20: U6.21 4145.21,2438.21 4151,2444 4177,2444 4236.5,2384.5 v1@5067.5,2384.5 ; N_JP1.1 5107,1674 N_R1.1 ; v1@5067.5,2384.5 v1(5068,2385) 5067,2385 v1@5067.5,2384.5
  Bottom Layer w20: v1(5068,2385) 5105,2348 N_JP1.1
TDI: N_JP1.9 N_R4.1 U6.24 | length 1467.9
  Top Layer w20: U6.24 v1(4663,2480.53) ; N_JP1.9 4705,1903.6 N_R4.1
  Bottom Layer w20: v1(4663,2480.53) 4663,2479 4705,2437 N_JP1.9
TDO: N_JP1.3 N_R2.1 U6.23 | length 1785.6
  Top Layer w20: U6.23 4273.48,2431 v1@4966,2431 ; v1(4966,2430) v1@4966,2431 ; v1@4966.5,2430.5 v1@4966,2431 ; N_JP1.3@4991,1686 N_JP1.3 5005,1874.6 N_R2.1 4976.4,1906.6 N_R2.1@4991,1892
  Bottom Layer w20: v1(4966,2430) 5005,2391 N_JP1.3
TMS: N_JP1.5 N_R3.1 U6.22 | length 1683.2
  Top Layer w20: U6.22@4176.7,2349.3 4186,2340 4856,2340 v1@4858,2338 ; U6.22 4176.7,2345.3 U6.22@4182,2340 ; N_R3.1 4862.4,1904.6 4905,1862 N_JP1.5 ; v1@4856,2339 v1(4859,2339)
  Bottom Layer w20: v1(4859,2339) 4905,2293 N_JP1.5
TXD: U5.10 U6.10 | length 2474.3
  Top Layer w20: U5.10 2044,3225 2067,3202 3064,3202 3160,3106 3333,3106 3341,3098 3341,2820 3394,2767 3394,2529 3442.46,2480.54 U6.10
VCC: A_C8.1 A_C9.1 A_C10.1 A_C11.1 A_R1.2 A_R2.2 A_R7.2 B_R1.1 B_R2.1 B_R3.1 C_C3.2 C_C4.1 D_C1.1 D_C2.1 D_C3.1 D_C4.1 E_C3.2 F_R1.2 G_JP1.2 J5.4 J6.1 N_JP1.4 N_JP1.7 N_R1.2 N_R2.2 N_R3.2 N_R4.2 U1.1 U1.8 U1.14 U1.16 U1.23 U1.24 U4.2 U5.16 U6.5 U6.17 U6.27 U6.38 | length 17712.5
  Top Layer w10: U5.16 U5.16@2344,3371 ; v1@2513.02,2625.44 cw(c2496.16,2608.16) 2520.3,2608.46 cw(c2544.44,2608.76) v1@2527.16,2625.62 ; v1(2520,2632.6) 2521.6,2504.4 2561,2465 U1.8
  Top Layer w20: v1(2080.4,2631.4) B_R3.1 ; B_R1.1@2360,2667.6 B_R1.1 ; B_R1.1@2365.4,2678 B_R1.1@2366.4,2679 ; v1(2366.4,2632.6) B_R2.1@2366.4,2780 ; B_R2.1@2366.4,2784 B_R2.1@2369.4,2787 ; E_C3.2@2460.12,3380 E_C3.2@2481,3400.88 ; A_C8.1@2626.6,2050 2626.6,2160.6 U1.14 ; A_C9.1@2631,2931.6 A_C9.1 ; U4.2@2729,4207 U4.2 ; U1.16 3088,2215 3105,2198 v1(3105,2037) ; U1.23 U1.24 3130,2615 3149,2634 3149,2718 3161,2730 3264,2730 3289.4,2755.4 A_C11.1 ; A_C10.1 3034.4,2052.6 3050,2037 3192,2037 3203,2048 A_R7.2@3198,2053 ; D_C1.1 3672.39,2638.02 3953.21,2638.02 4019.22,2572 ; J5.4 v1(3713.72,3196.28) ; 4047,2575.02 4050.72,2578.74 4050.72,2910.72 4112.4,2972.4 D_C3.1@4112.4,3001 ; D_C2.1@4051,2213.4 4051,2214 4019.22,2245.78 4019.22,2572 ; F_R1.2 F_R1.2@4265,2004 ; A_R1.2@4350,2114 A_R1.2 ; D_C4.1 4359.4,2531.6 4315.98,2575.02 4022.24,2575.02 4019.22,2572 ; N_R1.2@5105,1993 N_R1.2
  Top Layer w30: U5.16@2353,3327 2355,3325 3008,3325 3036,3353 3036,3942 3002,3976 C_C4.1 2887.12,4178.88 2862,4204 U4.2 ; 2477,3329 E_C3.2 ; v1(2520,2085) 2552,2053 A_C8.1 ; v1(2520,2632.6) v1(2520,3092) ; 2523.6,2950.6 A_C9.1 ; C_C3.2 U4.2@2729,4207 ; U1.1@2652,2823.4 A_C9.1@2652,2940 ; 3038,3401 5100,3401 5136,3437 5136,4199 5189,4252 5463,4252 5511.02,4203.98 J6.1 ; A_C11.1 v1(3289.4,2849) ; 3708,3401 3713.72,3395.28 v1(3713.72,3303) ; D_C3.1 4360,3000 4379,3019 4379,3396 4384,3401 ; v1(4177,2038) 4295,2038 4352,2095 A_R1.2 4684,2112 4707,2089 N_R4.2 4709,1995 5220,1995 5239,1976 5239,1512 5236,1509 ; 4260,2038 4265,2033 F_R1.2 ; A_R1.2@4350,2114 A_R2.2 ; 4774,1995 4773,1994 4773,1810 4805,1778 N_JP1.7 ; N_JP1.4 5005,1529 5025,1509 5962,1509 5980,1527 G_JP1.2
  Bottom Layer w30: v1(2080.4,2631.4) v1@2365.21,2631.4 ; v1(2366.4,2632.6) v1(2520,2632.6) v1(2520,2085) 2567,2038 v1(4177,2038) ; v1(2520,2862) 3276.4,2862 v1@3288.4,2850 ; v1(2520,3092) 2520,3319 2521,3320 v1(2521,3324) ; 3258.02,2862 cw(c3258.02,2817.62) v1(3289.4,2849) ; v1(3713.72,3196.28) 3713.72,3247 3713.72,3279 v1(3713.72,3303)
VOL: B_C8.1 U2.9 | length 821
  Top Layer w10: U2.9 v1@2137.87,2569.13 ; U2.9@2112.12,2569.13 cw(c2112.12,2541.12) v1@2131.93,2560.93 ; U2.9@2117.6,2569.13 ccw(c2117.6,2589.4) v1@2131.93,2575.07
  Top Layer w20: v1(2261,1999) B_C8.1
  Bottom Layer w20: v1(2139,2568) 2140,2568 2170,2538 2170,2014 2185,1999 v1(2261,1999)
VOR: B_C7.1 U2.8 | length 634.6
  Top Layer w10: v1(2250,2210) 2251,2210 v1@2256,2205 ; v1(2265,2569) 2315.87,2569 U2.8 2316.13,2569 2357,2569 ; v1@2272.07,2561.93 cw(c2289.14,2544.86) 2289.14,2569 cw(c2289.14,2593.14) v1@2272.07,2576.07
  Top Layer w20: v1(2250,2210) 2325,2210 B_C7.1
  Bottom Layer w20: 2247.93,2556.93 cw(c2265,2539.86) v1@2265,2564 ; v1(2250,2210) 2250,2211 2217,2244 2217,2526 2260,2569 v1(2265,2569)
pads on no net: G_JP1.3 G_JP1.4 G_JP1.6 G_JP1.10 J2.2 J2.3 J3.1 J3.9 J5.0 N_JP1.8 U2.10 U5.11 U5.12 U5.13 U5.14 U6.7 U6.8 U6.11 U6.25 U6.26 U6.29 U6.33 U6.37
copper on no net:
  other v2: 5347.51,2311.14 5593.36,3741.36 1807,3816 6015.34,4370.97 4685.59,4373.73 1807,4421
  other v3: 6280,1434 1540,4500 6277,4501
  other v4: 4680.82,3918.38 6015.82,3918.38
  other v5: 1781.02,2643.93 1781.02,3628.93
  other v6: 1771.62,1712.78 1535.62,1713.96
  other v8: 4144,3272
  other v9: 3309,3272
  other v10: 1541,1433

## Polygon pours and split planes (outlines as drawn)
GND on Top Layer "Top Layer-GND" (hatched 90Degree grid 0 track 28, remove dead copper, pour order 1000): 3296,2489 3296,2024 3831,2024 3831,2479
GND on Top Layer "Top Layer-GND 1" (hatched 90Degree grid 0 track 28, remove dead copper, pour order 1001): 3469,2706 3469,2593 3491.46,2558 3632,2558 3632,2695
GND on Top Layer "Top Layer-GND 2" (hatched 90Degree grid 0 track 28, pour order 1002): 3549,3079 3549,2846 3586,2809 3748,2809 3765,2826 3765,3087 3763,3085 3763,3172 3554,3172
GND on Top Layer "Top Layer-GND 3" (hatched 90Degree grid 0 track 28, pour order 1003): 3826,2819 3826,2399 4223.6,2399 4223.6,2824
GND on Top Layer "Top Layer-GND 4" (hatched 90Degree grid 0 track 28, pour order 1004): 2946,2518 2976,2518 2976,2036 2676,2036 2676,2515
GND on Top Layer "Top Layer-GND 5" (hatched 90Degree grid 0 track 28, remove dead copper, pour order 1005): 1885,2511 1455,2511 1407,2463 1407,1613 1467,1553 1860,1553 1904,1597 1904,1852 1957,1905 2396,1905 2441,1950 2441,2632.6 1945,2632.6 1945,2509
GND on Top Layer "Top Layer-GND 6" (hatched 90Degree grid 0 track 28, pour order 1006): 2059,3487 2243,3487 2243,3428 2059,3428
GND on Top Layer "Top Layer-GND 7" (hatched 90Degree grid 0 track 28, pour order 1007): 5219,3418 5219,2768 5315,2768 5315,3415
GND on Top Layer "Top Layer-GND 8" (hatched 90Degree grid 0 track 28, pour order 1008): 4465,3371 4425,3331 4425,2971 4390,2936 4331,2936 4306,2911 4306,2837 4330,2813 5093,2813 5127,2847 5127,3327 5098,3356 5086,3368
GND on Top Layer "Top Layer-GND 9" (hatched 90Degree grid 0 track 28, remove dead copper, pour order 1009): 4368,3415 4368,1972 2542,1972 2427,1857 1981,1857 1981,1554 1921,1494 1571,1494 1571,1337 6399,1337 6399,3423
GND on Top Layer "Top Layer-GND 10" (solid, remove dead copper, pour order 1010): 1446,2568 1871,2568 1871,3408 2079,3616 2079,3742 2851.09,3742 2851.09,3511 3036,3511 3036,3415 6430,3415 6430,4613 1432,4613
GND on Bottom Layer "Bottom Layer-GND" (hatched 90Degree grid 0 track 28, remove dead copper, pour order 1011): 1902,2518 1472,2518 1424,2470 1424,1620 1484,1560 1877,1560 1921,1604 1921,1859 1974,1912 2413,1912 2458,1957 2458,2639.6 1962,2639.6 1962,2516
GND on Bottom Layer "Bottom Layer-GND 1" (hatched 90Degree grid 0 track 28, pour order 1012): 3746,3305.17 3746,3238 4091,3238 4091,3306
GND on Bottom Layer "Bottom Layer-GND 2" (hatched 90Degree grid 0 track 28, pour order 1013): 3013,3374 3013,3079 3709,3079 3709,3401
GND on Bottom Layer "Bottom Layer-GND 3" (hatched 90Degree grid 0 track 28, pour order 1014): 4359,2725 5980,2725 5980,3349 4157,3349
GND on Bottom Layer "Bottom Layer-GND 4" (hatched 90Degree grid 0 track 28, remove dead copper, pour order 1015): 4516,4592 4516,1315 6320,1315 6413,1408 6413,4613 6365,4661 4527,4661
GND on Bottom Layer "Bottom Layer-GND 5" (hatched 90Degree grid 0 track 28, pour order 1016): 5780,2744 5780,1708 6017,1708 6017,2732.88
GND on Bottom Layer "Bottom Layer-GND 6" (hatched 90Degree grid 0 track 28, remove dead copper, pour order 1017): 3840,2816 3840,3117 4547,3117 4547,2725 3842,2725
GND on Bottom Layer "Bottom Layer-GND 7" (solid, pour order 1018): 2985,4633 4704,4633 4704,3340 3017.23,3340 2985,3360.02
GND on Bottom Layer "Bottom Layer-GND 8" (hatched 90Degree grid 0 track 28, remove dead copper, pour order 1019): 1404,3825 1404,3064 3036,3064 3036,3825
GND on Bottom Layer "Bottom Layer-GND 9" (hatched 90Degree grid 0 track 28, remove dead copper, pour order 1020): 2957.99,3360 2957.99,3069 4547,3069 4547,3416
GND on Bottom Layer "Bottom Layer-GND 10" (hatched 90Degree grid 0 track 28, remove dead copper, pour order 1021): 3475,2620 3475,2060 2568,2060 2568,2842 3472,2842
GND on Bottom Layer "Bottom Layer-GND 11" (hatched 90Degree grid 0 track 28, remove dead copper, pour order 1022): 3628,2730 3628,2263 4176,2263 4176,2749
GND on Bottom Layer "Bottom Layer-GND 12" (hatched 90Degree grid 0 track 28, remove dead copper, pour order 1023): 1437,3202 1437,2611 1475,2573 1895,2573 1895,3208
GND on Bottom Layer "Bottom Layer-GND 13" (hatched 90Degree grid 0 track 28, pour order 1024): 2467,2589.51 2467,1960.52 2400,1905 2400,2592
GND on Bottom Layer "Bottom Layer-GND 14" (hatched 90Degree grid 0 track 28, pour order 1025): 2441,2485 2441,2576 2425,2592 2311.78,2592
GND on Bottom Layer "Bottom Layer-GND 15" (hatched 90Degree grid 0 track 28, pour order 1026): 2108,2891 2108,2707 2265,2707 2298,2674 2447,2674 2467,2694 2467,2869 2450,2886 2131,2886
GND on Bottom Layer "Bottom Layer-GND 16" (hatched 90Degree grid 0 track 28, pour order 1027): 2432,1848 2567,1983 4200,1983 4200,1864 4183,1864 4200,1847
GND on Bottom Layer "Bottom Layer-GND 17" (hatched 90Degree grid 0 track 28, remove dead copper, pour order 1028): 4505,1671 4505,2661 4142.97,2661 4142.97,1668
GND on Bottom Layer "Bottom Layer-GND 18" (hatched 90Degree grid 0 track 28, remove dead copper, pour order 1029): 1981,1838 1981,1339 4605,1339 4605,1834.37
GND on Bottom Layer "Bottom Layer-GND 19" (hatched 90Degree grid 0 track 28, remove dead copper, pour order 1030): 1410,4640 3036,4640 3036,3804 1404,3804
GND on Bottom Layer "Bottom Layer-GND 20" (hatched 90Degree grid 0 track 28, remove dead copper, pour order 1031): 4549,3384 4549,2613 6010,2613 6010,3384
GND on Bottom Layer "Bottom Layer-GND 21" (hatched 90Degree grid 0 track 28, pour order 1032): 1628.31,1494 1929.08,1494 1981,1552 1981,1339 1537,1339

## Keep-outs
Keep-Out Layer:
  lines w10: 1400,4499 cw(c1542.5,4502.5) 1539,4645 6270,4644 ; 1403,4520 1401,1436 ccw(c1543.5,1443.5) 1551,1301 6282,1301 ; 6263,4645 cw(c6270.5,4502.5) 6413,4510 ; 6278,1301 ccw(c6270.5,1443.5) 6413,1451 6413,4512

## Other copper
Top Layer:
  text "高端、高速PCB设计文件与你共分享 PCB联盟网 www.pcbbar.com  QQ群:374116257" at 1203,5037 h196.85

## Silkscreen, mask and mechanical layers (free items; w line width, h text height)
Top Overlay:
  lines w10: 1403,3808 1738,3808 ; 1404,2491 1894,2491 1923,2520 1923,3180 1953,3210 1960,3210 3022,3210 ; 1871,3807 2017,3807 ; 1874,4401 3050,4401 3078,4373 ; 1908,3807 3055,3807 3075,3787 3075,3739 ; 1926,3841 3051,3841 3078,3868 3078,4373 ; 1962,3671 1962,3752 1962,3762 1968,3768 1989,3768 ; 1962,3681 1962,3663 1967,3658 1993,3658 ; 1975,3658 2267,3658 2272.91,3663.91 2272.91,3759.09 2264,3768 1978,3768 ; 3012,3210 3050,3210 3075,3235 3075,3750 ; 3075,3263 3075,3279 ; 3075,3333 3075,3374 ; 3078,4371 3078,4373 ; 3173,4219 3173,4298 3185,4310 3606,4310 3619,4297 3619,4205 3609,4195 3181,4195 3173,4203 3173,4234 ; 5005,4575 4970,4575 ; 5374,1965 6170,1965 ; 5396,2065 6171,2065 6171,1859 6168,1862 5376,1862 5374,1864 5374,2064 5375,2065 5415,2065 ; 5523,1863 5523,2065 ; 5683,1862 5683,2065 ; 5859,1865 5859,2065 ; 5885,1986 5926,1986 5929,1986 5983,2040 ; 6012,1864 6012,2065 ; 4970,4575 4957,4562 4957,4470 4971,4456 5794,4456 5807,4469 5807,4561 5793,4575 4970,4575 ; 1956,4434 1963,4427 2257,4427 2266,4436 2266,4519 2260,4525 1964,4525 1962,4525 1956,4519 1956,4434
  text "NOKIA 3310 LCD" at 4981,4479 h60
  text "power" at 1977,4463 h60
  text "MP3 Player" at 3403,4380 h80
  text "SD Card" at 3195,4224 h60
  text "RS232" at 1983,3680 h60
  text "MOSI" at 5391,1997 h36
  text "SCK" at 5556,1995 h36
  text "RET" at 5711,1993 h36
  text "MISO" at 6029,1993 h36
  text "GND" at 5396,1895 h36
  text "GND" at 5554,1893 h36
  text "VCC" at 6040,1893 h36
  text "GND" at 5709,1892 h36
  text "GND" at 5885,1890 h36
  text "VOL-" at 3775,1374 h60
  text "NEXT" at 2910,1368 h60
  text "VOL+" at 3341,1367 h60
  text "RESET" at 4175,1367 h60
  text "PREV" at 2475,1364 h60
  text "ST/PS" at 2043,1363 h60
  text "ISP" at 5680,1353 h60
  text "JTAG" at 4771,1349 h60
